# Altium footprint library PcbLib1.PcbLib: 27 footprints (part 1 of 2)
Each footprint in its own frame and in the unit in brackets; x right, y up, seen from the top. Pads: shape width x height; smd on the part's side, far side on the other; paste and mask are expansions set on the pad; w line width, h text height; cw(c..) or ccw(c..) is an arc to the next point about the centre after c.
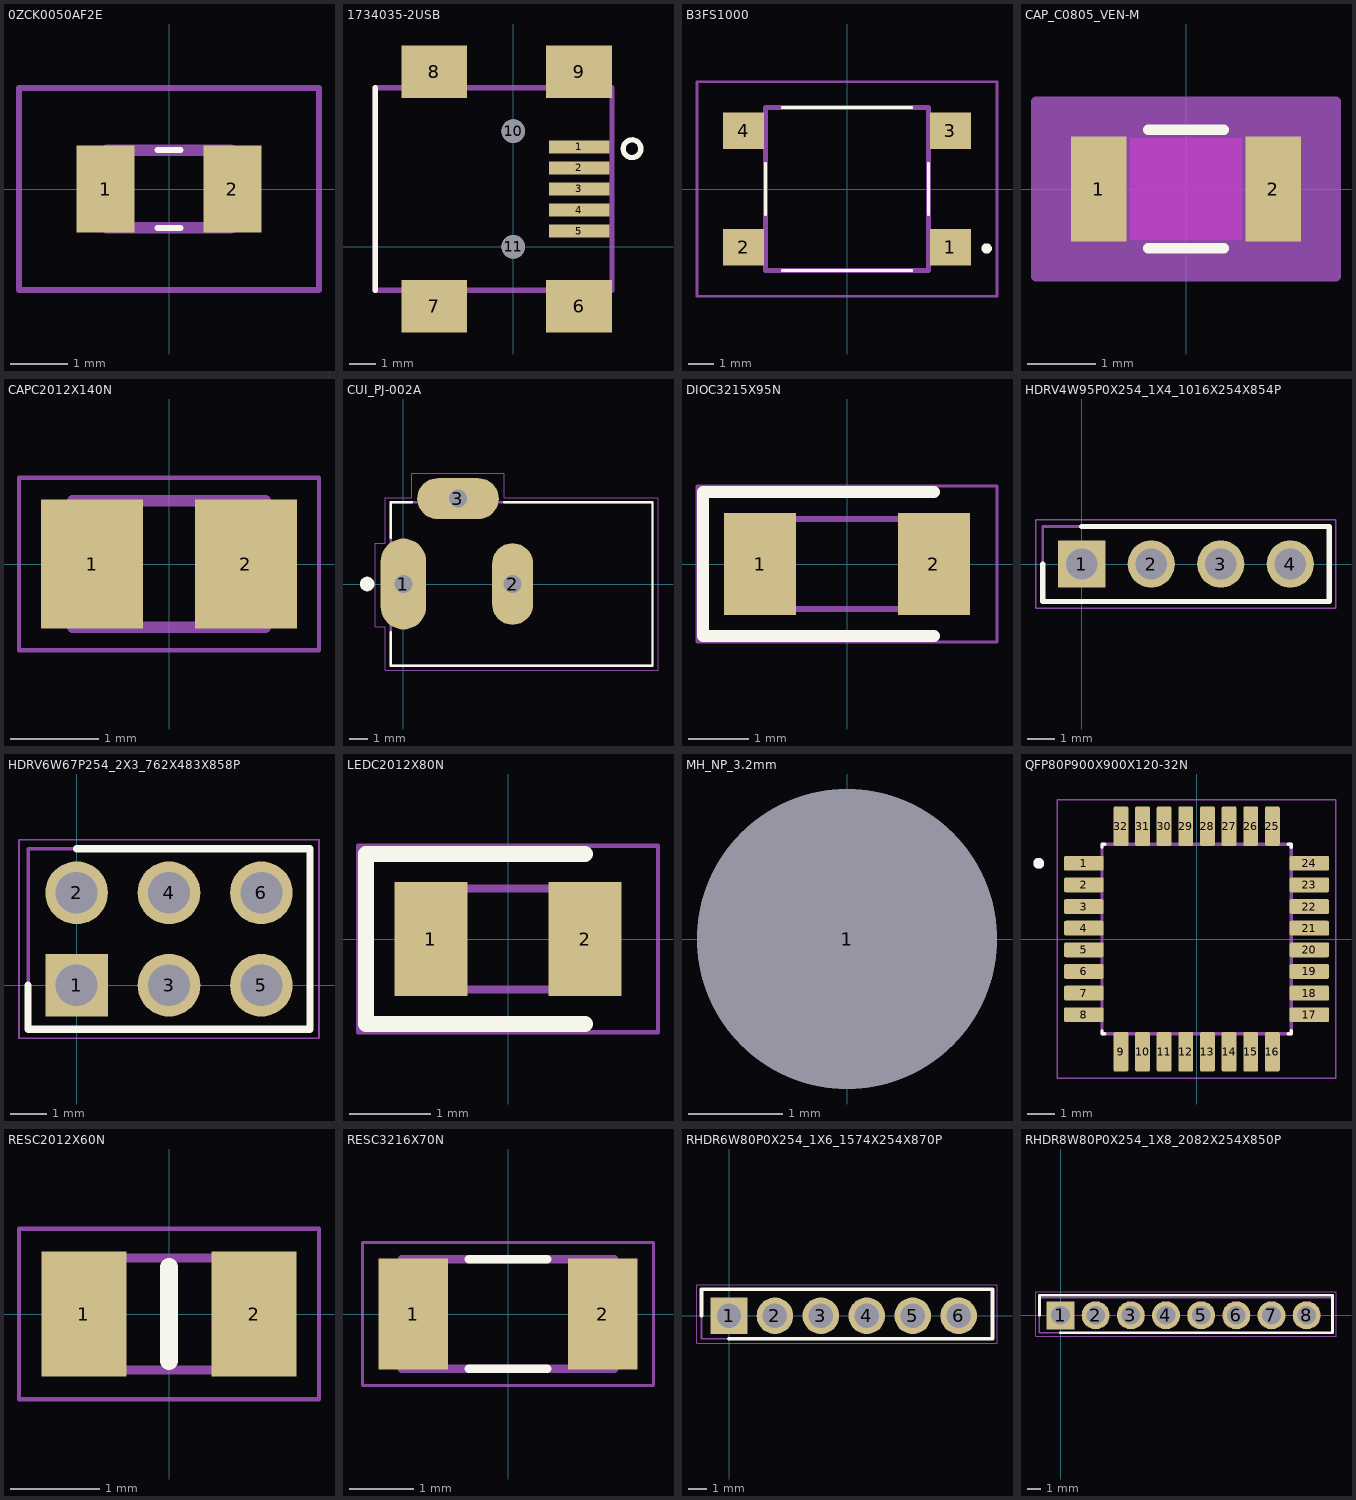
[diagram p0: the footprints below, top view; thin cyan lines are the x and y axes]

## 0ZCK0050AF2E [mm]
pads (2):
  rect 1x1.5 smd: 1(-1.1,0) 2(1.1,0)
Top Overlay:
  lines w0.1: -0.2,-0.675 0.2,-0.675 ; -0.2,0.675 0.2,0.675
Mechanical 15:
  lines w0.2: -1.075,-0.675 -1.075,0.675 1.075,0.675 1.075,-0.675 -1.075,-0.675
Mechanical 20:
  lines w0.1: -2.6,-1.75 -2.6,1.75 2.6,1.75 2.6,-1.75 -2.6,-1.75
3D body "0ZCK0050AF2E.stp": height 1.26, standoff 0.01, extent -1.075,-0.675 1.075,0.675

## 1734035-2USB [mm]
pads (11):
  rect 2.3x0.5 smd: 1(2.5,3.8) 2(2.5,3) 3(2.5,2.2) 4(2.5,1.4) 5(2.5,0.6)
  rect 2.5x2 smd: 6(2.5,-2.25) 7(-3,-2.25) 8(-3,6.65) 9(2.5,6.65)
  round 0.9 hole 0.9 unplated: 10(0,4.4) 11(0,0)
Top Overlay:
  circle w0.2: c4.512,3.731 r0.336
  lines w0.2: -5.25,-1.65 -5.25,6.05
Mechanical 13:
  lines w0.2: -5.25,-1.65 -5.25,6.05 3.75,6.05 3.75,-1.65 -5.25,-1.65
3D body "1734035-4.stp": height 4.14, standoff -0.95, extent -5.89,-2.76 3.31,7.14

## B3FS1000 [mm]
pads (4):
  rect 1.6x1.4 smd: 1(4,-2.25) 2(-4,-2.25) 3(4,2.25) 4(-4,2.25)
Top Overlay:
  lines w0.1: -3.15,-1 -3.15,1 ; -2.5,-3.15 2.5,-3.15 ; -2.5,3.15 2.5,3.15 ; 3.15,-1 3.15,1
  lines w0.2: 5.3,-2.3 cw(c5.4,-2.3) 5.5,-2.3 cw(c5.4,-2.3) 5.3,-2.3
Mechanical 15:
  lines w0.2: -3.15,-3.15 -3.15,3.15 3.15,3.15 3.15,-3.15 -3.15,-3.15
Mechanical 20:
  lines w0.1: -5.8,-4.15 -5.8,4.15 5.8,4.15 5.8,-4.15 -5.8,-4.15
3D body "B3FS-1000.stp": height 3, standoff -0.1, extent -4,-3.15 4,3.15

## CAP_C0805_VEN-M [mil]
pads (2):
  rect 32x60 smd paste+0 mask+0: 1(-50,0) 2(50,0)
Top Layer keep-out:
  region: -32,-27 -32,27 32,27 32,-27
Top Overlay:
  lines w6: -21.53,-34 21.53,-34 ; -21.53,34 21.53,34
Keep-Out Layer:
  region: -32,-29 -32,29 32,29 32,-29
Mechanical 13:
  circle w0: c-45,0 r3
  lines w1: -44,-29 -44,29 ; -44,-29 44,-29 ; -44,-29 -34,-29 -34,29 -44,29 ; -44,-29 -44,29 ; -44,29 44,29 ; 44,-29 44,29 ; 44,-29 44,29 ; 44,-29 34,-29 34,29 44,29
Mechanical 15:
  region: 86,-50 -86,-50 -86,50 86,50
  lines w6: -86,-50 86,-50 86,50 -86,50 -86,-50
3D body "CAP_C0805_VEN.step": height 12.01, standoff 0, extent -44.02,-29.02 44.02,29.02

## CAPC2012X140N [mm]
pads (2):
  rect 1.16x1.47 smd: 1(-0.875,0) 2(0.875,0)
Mechanical 13:
  lines w0.127: -1.1,-0.72 1.1,-0.72 1.1,0.72 -1.1,0.72 -1.1,-0.72
Mechanical 15:
  lines w0.05: -1.708,-0.983 1.708,-0.983 1.708,0.983 -1.708,0.983 -1.708,-0.983
3D body "C0805C220J5GAC.STEP": height 1.28, standoff 0.01, extent -1.016,-0.762 1.016,0.635

## CUI_PJ-002A [mm]
pads (3):
  oval 2.5x5 hole 1 square: 1(0,0)
  oval 2.25x4.5 hole 1 square: 2(6,0)
  oval 4.5x2.25 hole 1 square: 3(3,4.7)
Top Overlay:
  circle w0.4: c-2,0 r0.2
  lines w0.127: -0.7,-2.65 -0.7,-4.5 13.7,-4.5 13.7,4.5 5.55,4.5 ; -0.7,2.55 -0.7,4.5 0.45,4.5
Mechanical 13:
  lines w0.127: -0.7,-4.5 -0.7,4.5 13.7,4.5 13.7,-4.5 -0.7,-4.5
Mechanical 15:
  lines w0.05: -1.55,-2.35 -1,-2.35 -1,-4.75 14,-4.75 14,4.75 5.55,4.75 5.55,6.1 0.45,6.1 0.45,4.75 -1,4.75 -1,2.25 -1.55,2.25 -1.55,-2.35
3D body "step_temp.STEP": height 11, standoff -3.5, extent -0.7,-4.5 13.7,4.9

## DIOC3215X95N [mm]
pads (2):
  rect 1.2x1.7 smd: 1(-1.45,0) 2(1.45,0)
Top Overlay:
  lines w0.2: 1.45,-1.2 -2.4,-1.2 -2.4,1.2 1.45,1.2
Mechanical 15:
  lines w0.1: -1.6,0.15 -1,0.75 ; -1.6,-0.75 1.6,-0.75 1.6,0.75 -1.6,0.75 -1.6,-0.75
Mechanical 20:
  lines w0.05: -2.5,-1.3 2.5,-1.3 2.5,1.3 -2.5,1.3 -2.5,-1.3
3D body "CD1206-S01575.stp": height 0.95, standoff 0, extent -1.6,-0.75 1.6,0.75

## HDRV4W95P0X254_1X4_1016X254X854P [mm]
pads (4):
  rect 1.725x1.725 / inner round 1.725 / far side rect 1.725x1.725 hole 1.15: 1(0,0)
  round 1.725 hole 1.15: 2(2.54,0) 3(5.08,0) 4(7.62,0)
Top Overlay:
  lines w0.2: -1.42,0 -1.42,-1.37 9.04,-1.37 9.04,1.37 0,1.37
Mechanical 15:
  lines w0.1: -1.42,-1.37 9.04,-1.37 9.04,1.37 -1.42,1.37 -1.42,-1.37
Mechanical 20:
  lines w0.05: -1.67,-1.62 9.29,-1.62 9.29,1.62 -1.67,1.62 -1.67,-1.62
3D body "61300411121.stp": height 8.54, standoff -3.2, extent -1.27,-1.27 8.89,1.27

## HDRV6W67P254_2X3_762X483X858P [mm]
pads (6):
  rect 1.725x1.725 hole 1.15: 1(0,0)
  round 1.725 hole 1.15: 2(0,2.54) 3(2.54,0) 4(2.54,2.54) 5(5.08,0) 6(5.08,2.54)
Top Overlay:
  lines w0.2: -1.335,0 -1.335,-1.21 6.415,-1.21 6.415,3.75 0,3.75
Mechanical 13:
  lines w0.1: -1.335,-1.21 -1.335,3.75 6.415,3.75 6.415,-1.21 -1.335,-1.21
Mechanical 15:
  lines w0.05: -1.585,-1.46 -1.585,4 6.665,4 6.665,-1.46 -1.585,-1.46
3D body "67997-206HLF.stp": height 8.58, standoff -3.3, extent -1.27,-1.145 6.35,3.685

## LEDC2012X80N [mm]
pads (2):
  rect 0.9x1.4 smd: 1(-0.95,0) 2(0.95,0)
Top Overlay:
  lines w0.2: 0.95,-1.05 -1.75,-1.05 -1.75,1.05 0.95,1.05
Mechanical 15:
  lines w0.1: -1,0.208 -0.583,0.625 ; -1,-0.625 1,-0.625 1,0.625 -1,0.625 -1,-0.625
Mechanical 20:
  lines w0.05: -1.85,-1.15 1.85,-1.15 1.85,1.15 -1.85,1.15 -1.85,-1.15
3D body "LG R971-KN-1-0-20-R18.STEP": height 0.81, standoff 0.01, extent -1,-0.65 1,0.65

## MH_NP_3.2mm [mm]
pads (1):
  round 3.2 hole 3.2 mask+0.102: 1(0,0)

## QFP80P900X900X120-32N [mm]
height 1.2
pads (32):
  rrect25% 1.47x0.55 smd: 1(-4.17,2.8) 2(-4.17,2) 3(-4.17,1.2) 4(-4.17,0.4) 5(-4.17,-0.4) 6(-4.17,-1.2) 7(-4.17,-2) 8(-4.17,-2.8) 17(4.17,-2.8) 18(4.17,-2) 19(4.17,-1.2) 20(4.17,-0.4) 21(4.17,0.4) 22(4.17,1.2) 23(4.17,2) 24(4.17,2.8)
  rrect25% 0.55x1.47 smd: 9(-2.8,-4.17) 10(-2,-4.17) 11(-1.2,-4.17) 12(-0.4,-4.17) 13(0.4,-4.17) 14(1.2,-4.17) 15(2,-4.17) 16(2.8,-4.17) 25(2.8,4.17) 26(2,4.17) 27(1.2,4.17) 28(0.4,4.17) 29(-0.4,4.17) 30(-1.2,4.17) 31(-2,4.17) 32(-2.8,4.17)
Top Overlay:
  circle w0.2: c-5.84,2.8 r0.1
  lines w0.127: -3.5,-3.395 -3.5,-3.5 -3.395,-3.5 ; -3.5,3.395 -3.5,3.5 -3.395,3.5 ; 3.395,-3.5 3.5,-3.5 3.5,-3.395 ; 3.395,3.5 3.5,3.5 3.5,3.395
Mechanical 13:
  circle w0.2: c-5.84,2.8 r0.1
  lines w0.127: -3.5,-3.5 3.5,-3.5 3.5,3.5 -3.5,3.5 -3.5,-3.5
Mechanical 15:
  lines w0.05: -5.155,-5.155 5.155,-5.155 5.155,5.155 -5.155,5.155 -5.155,-5.155
3D body "step_temp.STEP": height 1.2, standoff 0, extent -4.5,-4.5 4.5,4.5

## RESC2012X60N [mm]
pads (2):
  rect 0.95x1.4 smd: 1(-0.95,0) 2(0.95,0)
Top Overlay:
  lines w0.2: 0,-0.525 0,0.525
Mechanical 15:
  lines w0.1: -1,-0.625 1,-0.625 1,0.625 -1,0.625 -1,-0.625
Mechanical 20:
  lines w0.05: -1.675,-0.95 1.675,-0.95 1.675,0.95 -1.675,0.95 -1.675,-0.95
3D body "RC0805FR-0710KL.stp": height 0.6, standoff 0, extent -1,-0.625 1,0.625

## RESC3216X70N [mm]
pads (2):
  rect 1.08x1.72 smd: 1(-1.47,0) 2(1.47,0)
Top Overlay:
  lines w0.127: -0.61,-0.85 0.61,-0.85 ; -0.61,0.85 0.61,0.85
Mechanical 13:
  lines w0.127: -1.65,-0.85 -1.65,0.85 1.65,0.85 1.65,-0.85 -1.65,-0.85
Mechanical 15:
  lines w0.05: -2.262,-1.112 -2.262,1.112 2.262,1.112 2.262,-1.112 -2.262,-1.112
3D body "FCR1206J10R.STEP": height 0.71, standoff 0.01, extent -1.6,-0.8 1.6,0.8

## RHDR6W80P0X254_1X6_1574X254X870P [mm]
pads (6):
  rect 2.025x2.025 hole 1.35: 1(0,0)
  round 2.025 hole 1.35: 2(2.54,0) 3(5.08,0) 4(7.62,0) 5(10.16,0) 6(12.7,0)
Top Overlay:
  lines w0.2: -1.52,0 -1.52,1.47 14.57,1.47 14.57,-1.27 0,-1.27
Mechanical 13:
  lines w0.1: -1.52,-1.27 -1.52,1.47 14.57,1.47 14.57,-1.27 -1.52,-1.27
Mechanical 15:
  lines w0.05: -1.77,-1.52 -1.77,1.72 14.82,1.72 14.82,-1.52 -1.77,-1.52
3D body "PPTC061LFBN-RC.stp": height 8.7, standoff -3.5, extent -1.52,-1.27 14.22,1.27

## RHDR8W80P0X254_1X8_2082X254X850P [mm]
pads (8):
  rect 2.025x2.025 hole 1.35: 1(0,0)
  round 2.025 hole 1.35: 2(2.54,0) 3(5.08,0) 4(7.62,0) 5(10.16,0) 6(12.7,0) 7(15.24,0) 8(17.78,0)
Top Overlay:
  lines w0.2: -1.52,0 -1.52,1.455 19.65,1.455 19.65,-1.27 0,-1.27
Mechanical 13:
  lines w0.1: -1.52,-1.27 -1.52,1.27 19.65,1.27 19.65,-1.27 -1.52,-1.27
Mechanical 15:
  lines w0.05: -1.77,-1.52 -1.77,1.705 19.9,1.705 19.9,-1.52 -1.77,-1.52
3D body "PPTC081LFBN-RC.stp": height 8.5, standoff -3.5, extent -1.52,-1.27 19.3,1.27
